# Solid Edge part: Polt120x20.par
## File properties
Author: Türk
Template: Iso Part.par
Last saved by: Türk
Revision: 9
Application: Solid Edge
Accuracy: 0,990
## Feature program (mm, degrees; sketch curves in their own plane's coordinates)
thread "unnamed Thread 1"
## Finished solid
Body 1: solid body, 23 faces, 45 edges, 24 vertices.
  Faces by surface: plane 21, cylinder 2
  Edges by curve: line 42, circle 3
Bounding box of the edges (mm): 24.000 x 139.500 x 27.713, from (-12, -10, -13.8564) to (12, 129.5, 13.8564).
Cylindrical faces by radius (mm): R10 x2
Planar faces by outward normal: +x 1, +y 2, -x 1, -y 1, oblique 16
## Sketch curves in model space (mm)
circle centre (0, 0, 0) radius 13.8564
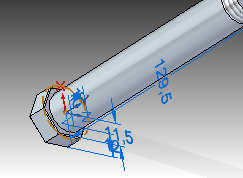
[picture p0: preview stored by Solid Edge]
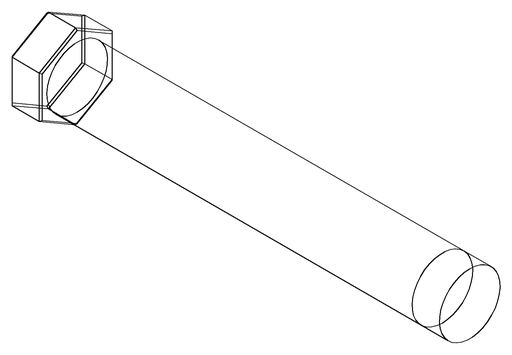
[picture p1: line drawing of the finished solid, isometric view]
